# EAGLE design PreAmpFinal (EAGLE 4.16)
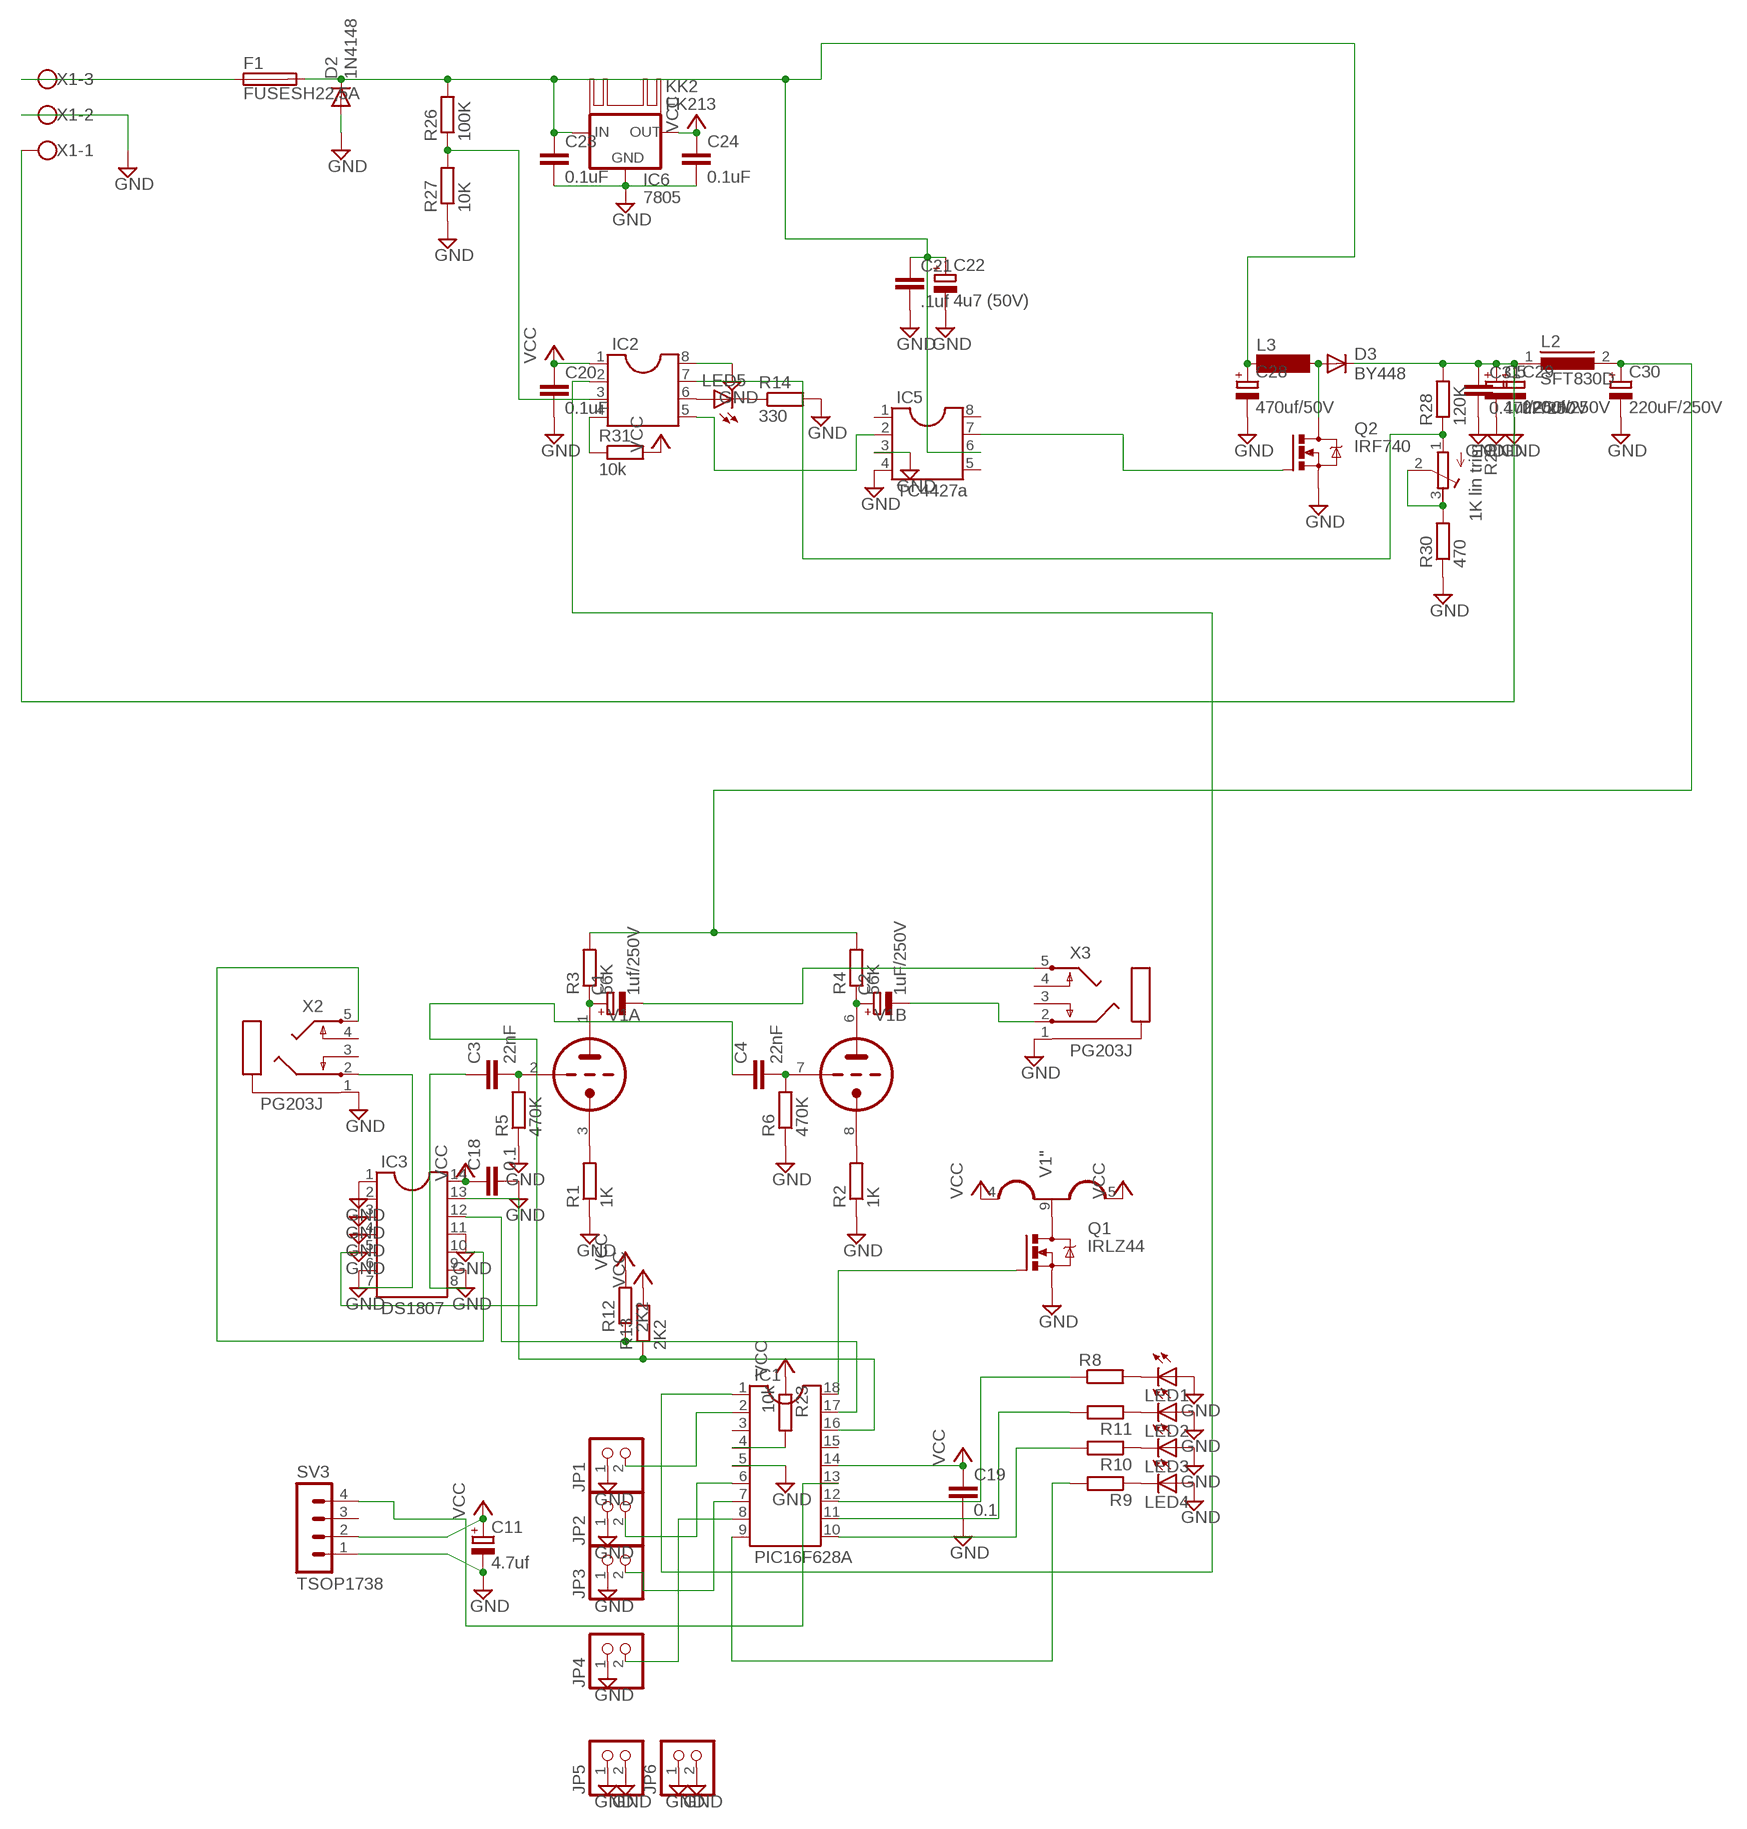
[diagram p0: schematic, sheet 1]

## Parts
C1  1uf/250V  CPOL-EUE2.5-7  [E2,5-7]
C2  1uF/250V  CPOL-EUE2.5-7  [E2,5-7]
C3  22nF  C7.5/4  [C7.5B4]
C4  22nF  C7.5/4  [C7.5B4]
C5  1uf/250V  CPOL-EUE2.5-7  [E2,5-7]
C11  4.7uf  CPOL-EUE2-5  [E2-5]
C18  0.1  C2.5/2  [C2.5-2]
C19  0.1  C2.5/2  [C2.5-2]
C20  0.1uF  C2.5/2  [C2.5-2]
C21  .1uf  C2.5/2  [C2.5-2]
C22  4u7 (50V)  CPOL-EUE2.5-5  [E2,5-5]
C23  0.1uF  C2.5/2  [C2.5-2]
C24  0.1uF  C2.5/2  [C2.5-2]
C28  470uf/50V  CPOL-EUE5-13  [E5-13]
C29  220uf/250V  CPOL-EUE10-22.5  [EB22,5D]
C30  220uF/250V  CPOL-EUE10-22.5  [EB22,5D]
C31  0.47uF/250V  C22/6  [C20.5B4]
D2  1N4148  [DO35-10]
D3  BY448  [SOD57-10]
F1  FUSESH22,5A  [SH22,5A]
IC1  PIC16F628A  DIL18S  [SOCKED-18]
IC2  DIL8S  [SOCKED-08]
IC3  DS1807  DIL14S  [SOCKED-14]
IC5  TC4427a  DIL8S  [SOCKED-08]
IC6  7805  78XXS  [78XXS]
JP1  PINHD-1X2  [1X02]
JP2  PINHD-1X2  [1X02]
JP3  PINHD-1X2  [1X02]
JP4  PINHD-1X2  [1X02]
JP5  PINHD-1X2  [1X02]
JP6  PINHD-1X2  [1X02]
KK2  FK213  [FK213]
L2  SFT830D  [SFT830D]
L3  18RXXX  [18R]
LED1  LED5MM  [LED5MM]
LED2  LED5MM  [LED5MM]
LED3  LED5MM  [LED5MM]
LED4  LED5MM  [LED5MM]
LED5  LED5MM  [LED5MM]
Q1  IRLZ44  IRF740  [TO220BV]
Q2  IRF740  [TO220BV]
R1  1K  R-EU_0204/7  [0204/7]
R2  1K  R-EU_0204/7  [0204/7]
R3  56K  R-EU_0204/7  [0204/7]
R4  56K  R-EU_0204/7  [0204/7]
R5  470K  R-EU_0204/7  [0204/7]
R6  470K  R-EU_0204/7  [0204/7]
R8  R-EU_0204/7  [0204/7]
R9  R-EU_0204/7  [0204/7]
R10  R-EU_0204/2V  [0204V]
R11  R-EU_0204/2V  [0204V]
R12  2K2  R-EU_0204/7  [0204/7]
R13  2K2  R-EU_0204/7  [0204/7]
R14  330  R-EU_0204/7  [0204/7]
R23  10k  R-EU_0204/7  [0204/7]
R26  100K  R-EU_0204/7  [0204/7]
R27  10K  R-EU_0204/7  [0204/7]
R28  120K  R-EU_0207/12  [0207/12]
R29  1K lin trim  R-TRIMM3339P  [RTRIM3339P]
R30  470  R-EU_0204/7  [0204/7]
R31  10k  R-EU_0204/7  [0204/7]
SV3  TSOP1738  MA04-1  [MA04-1]
V1  12AU7-P  [NOVAL]
X1  W237-3E  [W237-3E]
X2  PG203J  [PG203J]
X3  PG203J  [PG203J]

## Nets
GND: C5.- C11.- C18.2 C19.2 C20.2 C21.2 C22.- C23.2 C24.2 C28.- C29.- C30.- C31.2 D2.A IC1.5 IC2.8 IC3.1 IC3.2 IC3.3 IC3.4 IC3.6 IC3.9 IC3.11 IC5.3 IC5.4 IC6.GND JP1.1 JP2.1 JP3.1 JP4.1 JP5.1 JP5.2 JP6.1 JP6.2 LED1.A LED2.A LED3.A LED4.A Q1.S Q2.S R1.1 R2.1 R5.1 R6.1 R14.2 R27.1 R30.1 SV3.1 X1.2 X2.1 X3.1
N$1: C1.+ R3.1 V1.1(A:TA)
N$2: C2.+ R4.1 V1.6(B:TA)
N$3: R1.2 V1.3(A:TK)
N$4: R2.2 V1.8(B:TK)
N$5: Q1.D V1.9(":H2)
N$6: C3.2 R5.2 V1.2(A:TG)
N$7: C4.2 R6.2 V1.7(B:TG)
N$8: C30.+ L2.2 R3.2 R4.2
N$9: C3.1 IC3.8
N$10: IC2.4 R31.1
N$11: IC1.18 Q1.G
N$12: IC1.13 SV3.4
N$13: C2.- X3.2
N$14: LED1.K(C) R8.2
N$15: IC5.7 Q2.G
N$16: LED2.K(C) R11.1
N$17: LED3.K(C) R10.1
N$18: LED4.K(C) R9.1
N$19: IC1.2 JP1.2
N$22: F1.1 X1.3
N$23: IC1.12 R8.1
N$24: IC1.1 IC2.2
N$25: C4.1 IC3.5
N$26: IC1.17 IC3.12 R12.1
N$27: IC1.16 IC3.13 R13.1
N$28: IC3.7 X2.2
N$29: IC3.10 X2.5
N$30: IC1.11 R11.2
N$31: IC1.10 R10.2
N$32: IC2.6 LED5.A
N$33: IC1.9 R9.2
N$34: LED5.K(C) R14.1
N$35: C5.+ C29.+ C31.1 D3.C L2.1 R28.2 X1.1
N$36: C1.- X3.5
N$37: IC1.6 JP2.2
N$38: IC1.7 JP3.2
N$39: IC1.8 JP4.2
N$44: IC1.4 R23.2
N$48: IC2.5 IC5.2
N$49: IC2.3 R26.1 R27.2
N$53: IC2.7 R28.1 R29.1(E)
N$54: R29.2(S) R29.3(A) R30.2
N$56: D3.A L3.2 Q2.D
N$57: C21.1 C22.+ C23.1 C28.+ D2.C F1.2 IC5.6 IC6.IN L3.1 R26.2
VCC: C11.+ C18.1 C19.1 C20.1 C24.1 IC1.14 IC2.1 IC3.14 IC6.OUT R12.2 R13.2 R23.1 R31.2 SV3.2 V1.4(":H1) V1.5(":H3)
Unconnected: IC1.3 IC1.15 IC5.1 IC5.5 IC5.8 SV3.3 X2.3 X2.4 X3.3 X3.4

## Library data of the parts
C1 C2 C5 C11 C22 C28-C30 = rcl:CPOL-EU: POLARIZED CAPACITOR, European symbol
C3 C4 C18 C19 C31 = capacitor-HV:C: CAPACITOR
C20 C21 C23 C24 = capacitor-wima:C: CAPACITOR
D2 = diode:1N4148: DIODE
D3 = diode:BY448: DIODE
F1 = fuse:FUSE: Fuse
IC1 = ic-package:DIL18: Dual In Line
IC2 IC5 = ic-package:DIL8: Dual In Line
IC3 = ic-package:DIL14: Dual In Line
IC6 = v-reg:78XXS: VOLTAGE REGULATOR
JP1-JP6 = pinhead:PINHD-1X2: PIN HEADER
KK2 = heatsink:FK213: HEATSINK
L2 = inductors:SFT830D: INDUCTOR
L3 = inductor-neosid:18RXXX
LED1-LED5 = led:LED: LED
Q1 Q2 = transistor-power:IRF740: N-CHANNEL MOS FET
R1-R6 R8-R14 R23 R26-R28 R30 R31 = rcl:R-EU_: RESISTOR, European symbol
R29 = rcl:R-TRIMM: Trimm resistor
SV3 = con-lstb:MA04-1: PIN HEADER
V1 = tubes:12AU7-P
X1 = con-wago-508:W237-3E: WAGO SREW CLAMP
X2 X3 = con-hirschmann:PG203J: MIC/HEADPHONE JACK KS-S stereo microphone/headphone jack PG203JN (Schukat)

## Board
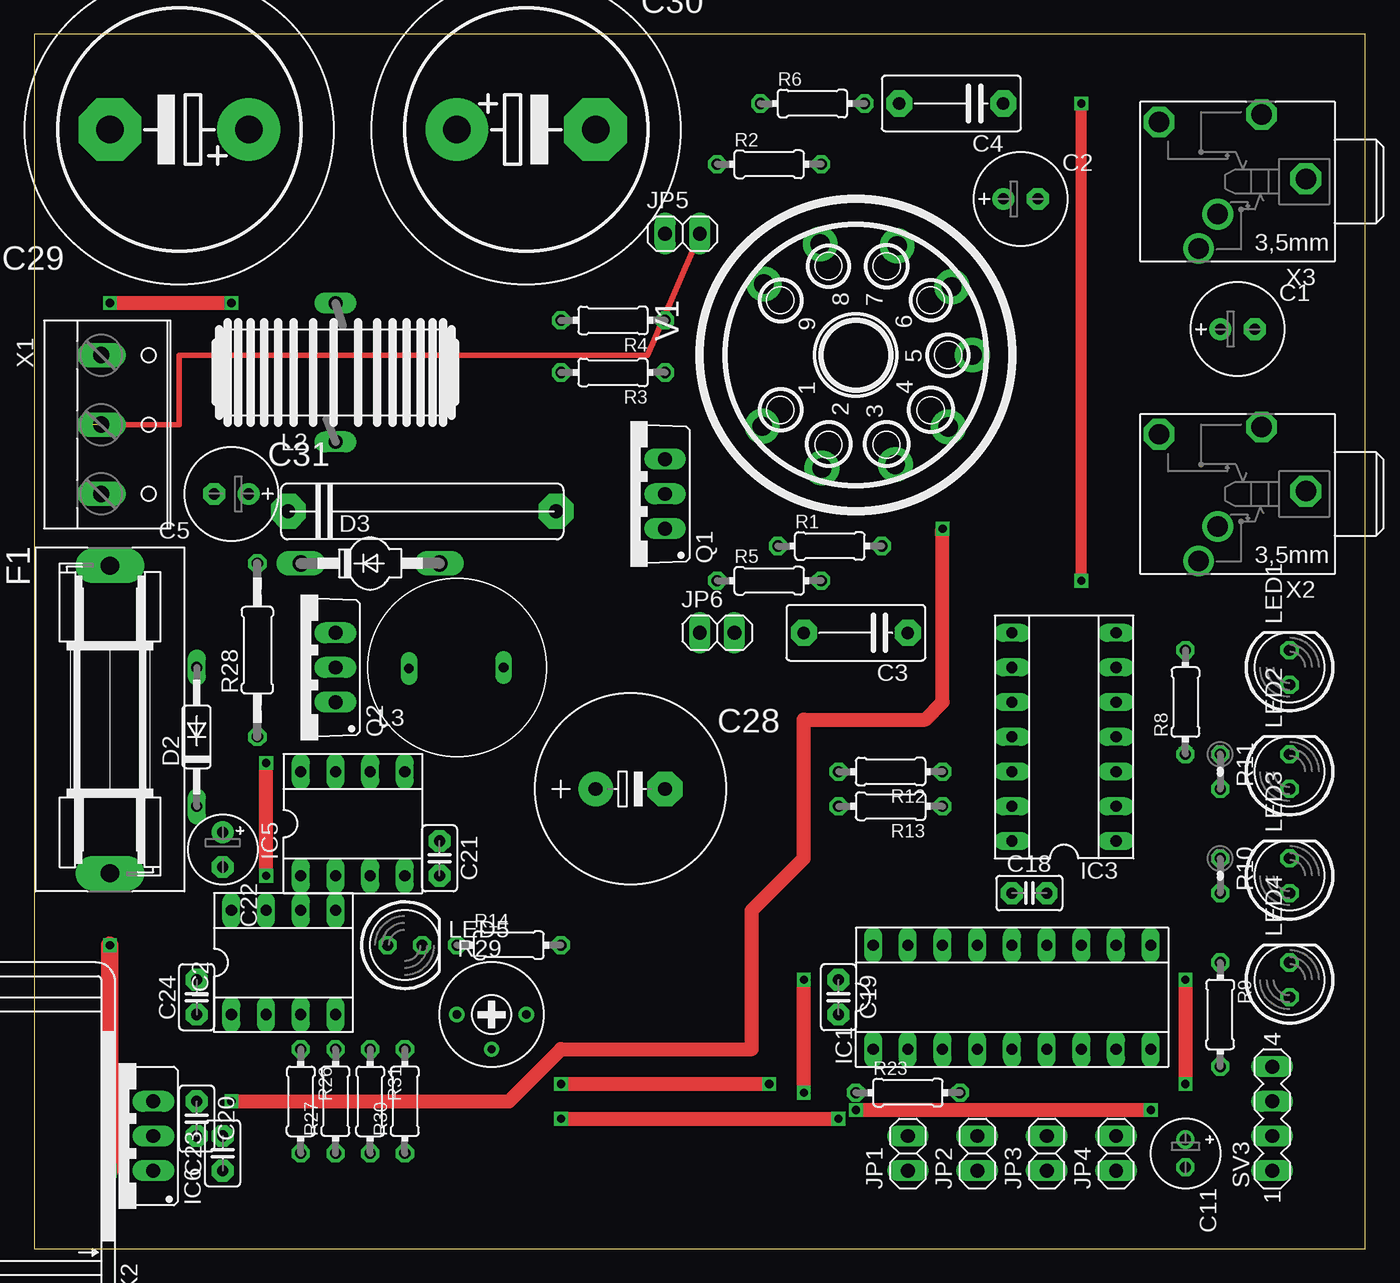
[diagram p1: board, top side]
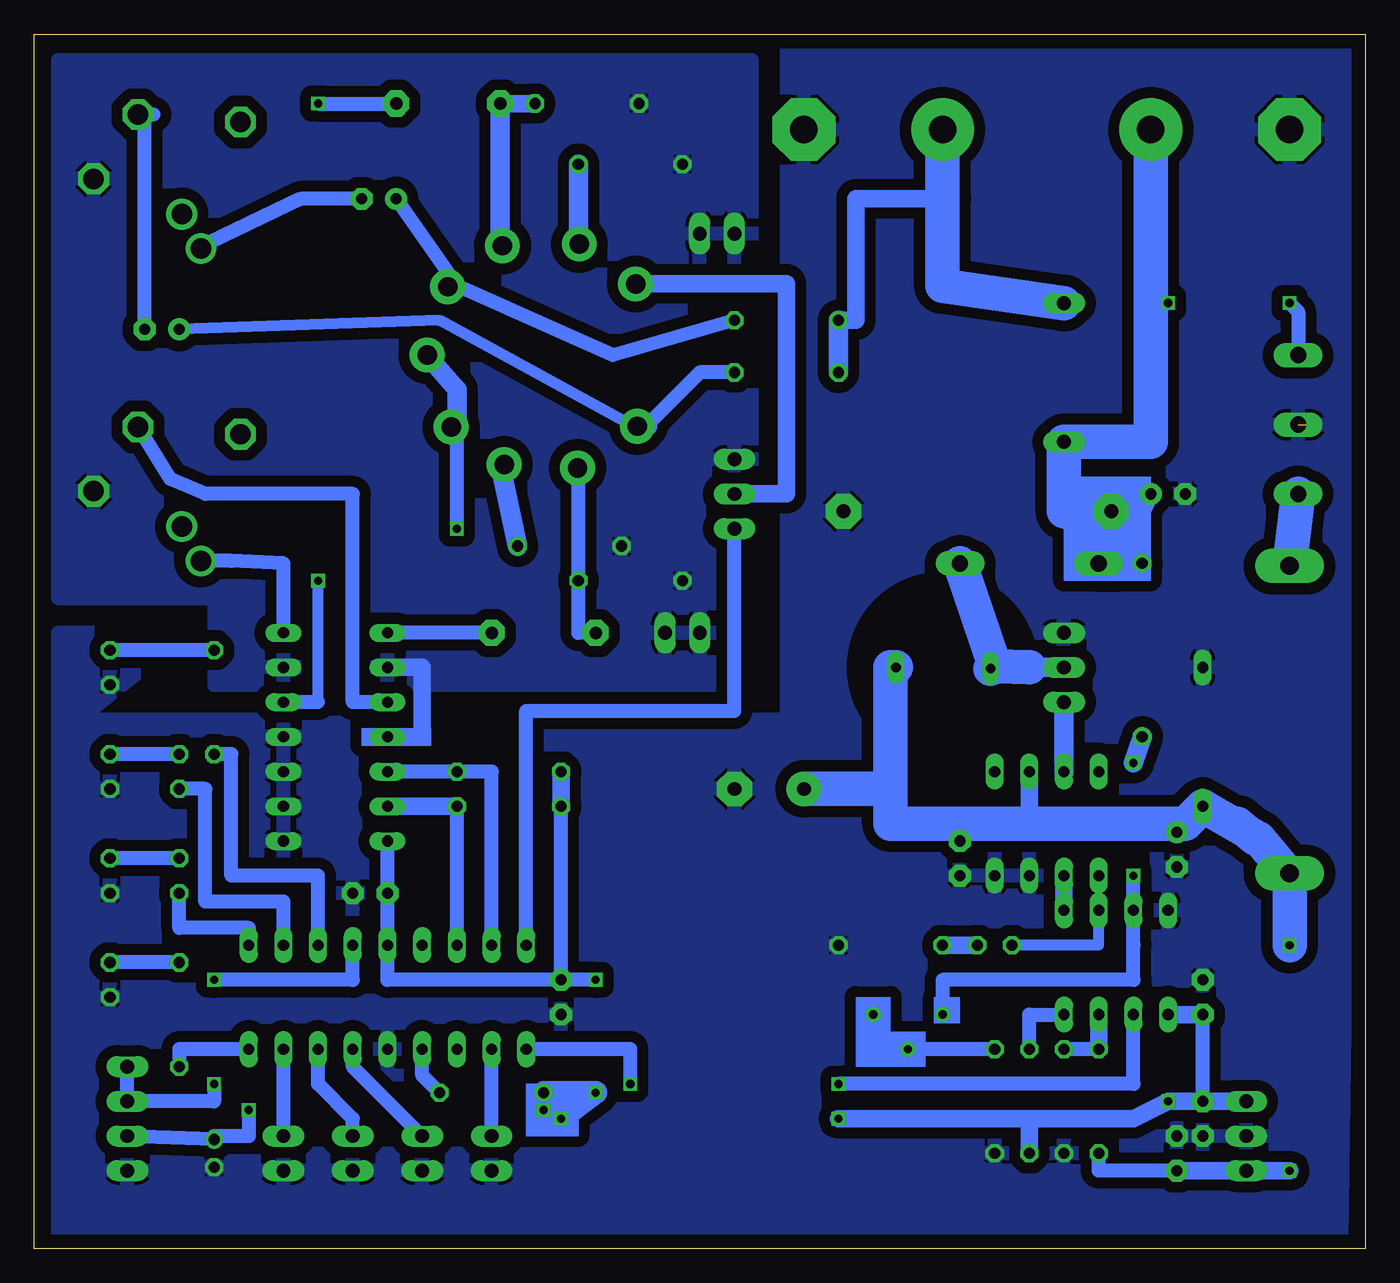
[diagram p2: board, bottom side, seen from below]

Size 97.46 x 88.89 mm. Coordinates in mm from the lower left corner, seen from the top.
Outline: 0,0 97.46,0 97.46,88.89 0,88.89 0,0
Copper layers (1*16): Top 0.035mm / dielectric 1.5mm / Bottom 0.035mm
Design rules "default": minimum track width 10mil, minimum drill 24mil, track to track 8mil, track to pad 8mil, pad to pad 8mil, via to via 8mil, smd to smd 8mil, copper to edge 40mil, drill to drill 8mil, minimum pad ring 10mil, minimum via ring 8mil, stop-mask expansion 4mil, vias tented up to drill 0mil, thermal gap 10mil
bRestrict: area 25.3,36.9 to 36.6,48.2

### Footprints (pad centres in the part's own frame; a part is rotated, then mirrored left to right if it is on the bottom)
E2,5-7 = drill 0.813 pad 1.6 round: + -1.27,0 | drill 0.813 pad 1.6 octagon: - 1.27,0
C7.5B4 = drill 0.914 pad 1.905 octagon: 1 -3.81,0; 2 3.81,0
E2-5 = drill 0.813 pad 1.27 round: + -1.016,0 | drill 0.813 pad 1.27 octagon: - 1.016,0
C2.5-2 = drill 0.813 pad 1.6 octagon: 1 -1.27,0; 2 1.27,0
E2,5-5 = drill 0.813 pad 1.6 round: + -1.27,0 | drill 0.813 pad 1.6 octagon: - 1.27,0
E5-13 = drill 1.016 pad 2.54 round: + -2.54,0 | drill 1.016 pad 2.54 octagon: - 2.54,0
EB22,5D = drill 2.007 pad 4.597 round: + -5.08,0 | drill 2.007 pad 4.597 octagon: - 5.08,0
C20.5B4 = drill 1.016 pad 2.54 octagon: 1 -9.803,0; 2 9.803,0
DO35-10 = drill 0.813 long: A 5.08,0; C -5.08,0
SOD57-10 = drill 1.194 long: A 5.08,0; C -5.08,0
SH22,5A = drill 1.321 pad 2.54 long: 1 -11.252,0; 2 11.252,0
SOCKED-18 = drill 0.813 long: 1 -10.16,-3.81; 2 -7.62,-3.81; 3 -5.08,-3.81; 4 -2.54,-3.81; 5 0,-3.81; 6 2.54,-3.81; 7 5.08,-3.81; 8 7.62,-3.81; 9 10.16,-3.81; 10 10.16,3.81; 11 7.62,3.81; 12 5.08,3.81; 13 2.54,3.81; 14 0,3.81; 15 -2.54,3.81; 16 -5.08,3.81; 17 -7.62,3.81; 18 -10.16,3.81
SOCKED-08 = drill 0.813 long: 1 -3.81,-3.81; 2 -1.27,-3.81; 3 1.27,-3.81; 4 3.81,-3.81; 5 3.81,3.81; 6 1.27,3.81; 7 -1.27,3.81; 8 -3.81,3.81
SOCKED-14 = drill 0.813 long: 1 -7.62,-3.81; 2 -5.08,-3.81; 3 -2.54,-3.81; 4 0,-3.81; 5 2.54,-3.81; 6 5.08,-3.81; 7 7.62,-3.81; 8 7.62,3.81; 9 5.08,3.81; 10 2.54,3.81; 11 0,3.81; 12 -2.54,3.81; 13 -5.08,3.81; 14 -7.62,3.81
78XXS = drill 1.016 long: GND 0,-2.54; IN -2.54,-2.54; OUT 2.54,-2.54
1X02 = drill 1.016 long: 1 -1.27,0; 2 1.27,0
SFT830D = drill 1.016 long: 1 -5.08,0; 2 5.08,0
18R = drill 0.7 long: 1 -3.415,0; 2 3.502,0.087
LED5MM = drill 0.813 octagon: A -1.27,0; K 1.27,0
TO220BV = drill 1.016 long: D 0,-2.54; G -2.54,-2.54; S 2.54,-2.54
0204/7 = drill 0.813 octagon: 1 -3.81,0; 2 3.81,0
0204V = drill 0.813 octagon: 1 -1.27,0; 2 1.27,0
0207/12 = drill 0.813 octagon: 1 -6.35,0; 2 6.35,0
RTRIM3339P = drill 0.61 round: 1 -2.54,0; 2 0,-2.54; 3 2.54,0
MA04-1 = drill 1.016 long: 1 -3.81,0; 2 -1.27,0; 3 1.27,0; 4 3.81,0
NOVAL = drill 1.422 pad 2.54 round: 1 5.207,-6.858; 2 8.254,-2.484; 3 8.004,2.893; 4 5.258,6.77; 5 0,8.524; 6 -5.004,7.024; 7 -8.004,3.02; 8 -8.127,-2.611; 9 -5.207,-6.731
W237-3E = drill 1.194 long: 1 -5.08,-0.635; 2 0,-0.635; 3 5.08,-0.635
PG203J = drill 1.499 octagon: 1 -5.004,-0.203; 4 5.74,-4.369; 5 -1.753,-4.902 | drill 1.499 round: 2 2.845,4.902; 3 1.448,2.388

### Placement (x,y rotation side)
C1  88.1,67.31 0 top
C2  72.22,76.83 0 top
C3  60.16,45.08 180 top
C4  67.14,83.81 180 top
C5  14.44,55.24 180 top
C11  84.29,6.98 270 top
C18  72.86,26.03 0 top
C19  58.89,18.41 270 top
C20  11.9,9.52 270 top
C21  29.68,28.57 270 top
C22  13.81,29.21 270 top
C23  13.81,6.98 90 top
C24  11.9,18.41 90 top
C28  43.65,33.65 0 top
C29  10.63,81.91 180 top
C30  36.03,81.91 0 top
C31  28.41,53.97 0 top
D2  11.9,37.46 90 top
D3  24.6,50.16 0 top
F1  5.55,38.73 270 top
IC1  71.59,18.41 0 top
IC2  18.25,20.95 0 top
IC3  75.4,37.46 90 top
IC5  23.33,31.11 0 top
IC6  6.18,8.25 90 top
JP1  63.97,6.98 90 top
JP2  69.05,6.98 90 top
JP3  74.13,6.98 90 top
JP4  79.21,6.98 90 top
JP5  47.46,74.29 0 top
JP6  50,45.08 0 top
KK2  4.92,8.25 90 top
L2  22.06,64.13 90 top
L3  30.95,42.54 180 top
LED1  91.91,42.54 90 top
LED2  91.91,34.92 90 top
LED3  91.91,27.3 90 top
LED4  91.91,19.68 90 top
LED5  27.14,22.22 0 top
Q1  43.65,55.24 90 top
Q2  19.52,42.54 90 top
R1  58.25,51.43 0 top
R2  53.81,79.37 0 top
R3  42.38,64.13 180 top
R4  42.38,67.94 180 top
R5  53.81,48.89 0 top
R6  56.98,83.81 0 top
R8  84.29,40 90 top
R9  86.83,17.14 270 top
R10  86.83,27.3 270 top
R11  86.83,34.92 270 top
R12  62.7,34.92 180 top
R13  62.7,32.38 180 top
R14  34.76,22.22 0 top
R23  63.97,11.43 0 top
R26  19.52,10.79 270 top
R27  22.06,10.79 90 top
R28  16.34,43.81 90 top
R29  33.49,17.14 0 top
R30  27.14,10.79 90 top
R31  24.6,10.79 270 top
SV3  90.64,9.52 90 top
V1  60.16,65.4 270 top
X1  5.55,60.32 270 top
X2  88.1,55.24 180 top
X3  88.1,78.1 180 top

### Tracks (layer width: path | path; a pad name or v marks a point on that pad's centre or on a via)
GND  (1 unrouted)
  Top 0.406: JP5.2 44.92,65.4 10.63,65.4 10.63,60.32 4.28,60.32
  Bottom 1.27: IC3.11 69.05,37.46 69.05,42.54 IC3.9
  pour Bottom (isolate 0.813): 42.38,88.26 42.38,38.73 95.72,38.73 95.72,0.63 1.74,0.63 0.47,88.26
  pour Bottom (isolate 0.813): 44.92,86.99 95.72,86.99 95.72,47.62 84.29,47.62 84.29,41.27 44.92,41.27
  pour Bottom (isolate 0.813): 86.19,45.08 95.72,45.08 95.72,37.46
N$1
  Bottom 0.813: V1.1 53.17,60.32 53.81,60.32 67.78,67.94 C1.+
  Bottom 1.016: 52.54,60.19 52.54,60.32 48.73,64.13 R3.1
  Bottom 1.422: 52.54,60.19 V1.1
N$2
  Bottom 1.016: 66.51,70.48 67.14,70.48 | 66.51,70.48 55.08,65.4 R4.1 | 66.51,70.48 C2.+
  Bottom 1.422: V1.6 67.14,70.4 67.14,70.48
N$3
  Bottom 1.422: V1.3 63.34,57.4 R1.2
N$4
  Bottom 1.016: 57.62,73.66 57.55,73.58 V1.8
  Bottom 1.422: R2.2 57.62,73.66 57.62,73.02
N$5
  Bottom 1.016: 53.81,70.48 53.81,70.61 V1.9
  Bottom 1.27: 53.81,70.61 42.38,70.61 42.38,55.24 Q1.D
N$6
  Bottom 1.016: C3.2 57.62,45.08 R5.2 57.62,57.14 | 57.62,57.14 57.62,57.78 | 57.62,57.14 57.62,57.15
  Bottom 1.422: 57.62,57.15 V1.2
N$7
  Bottom 1.27: C4.2 R6.2
  Bottom 1.422: 63.34,73.4 63.34,73.02 | V1.7 63.34,73.4 | 63.34,73.4 C4.2
N$8
  Bottom 1.27: R4.2 37.3,67.94 37.3,76.83 30.95,76.83
  Bottom 1.422: R4.2 R3.2
  Bottom 2.54: L2.2 30.95,70.48 30.95,76.83 C30.+
N$9
  Bottom 1.016: C3.1 IC3.8
N$10
  Bottom 1.016: R31.1 24.6,17.14 IC2.4
N$11
  Bottom 1.016: IC1.18 61.43,39.36 46.19,39.36 Q1.G
N$12  (via drill 0.6)
  Top 1.016: v84.29,19.68 v84.29,12.06
  Bottom 1.016: SV3.4 90.64,10.79 84.29,10.79 v84.29,12.06 | IC1.13 74.13,19.68 v84.29,19.68
N$13
  Bottom 1.016: X3.2 85.56,73.2 77.94,76.83 C2.-
N$14
  Bottom 1.016: R8.2 LED1.K
N$15
  Bottom 1.422: IC5.7 Q2.G
N$16
  Bottom 1.016: R11.1 LED2.K
N$17
  Bottom 1.016: R10.1 LED3.K
N$18
  Bottom 1.016: R9.1 LED4.K
N$19
  Bottom 1.016: JP1.2 IC1.2
N$22
  Bottom 2.54: X1.3 5.55,50.16 F1.1
N$23  (via drill 0.6)
  Bottom 1.016: IC1.12 76.67,27.3 83.02,27.3 83.02,36.19 R8.1
  other vias: 84.29,36.19 84.29,36.19
N$24  (via drill 0.6)
  Top 1.016: v38.57,12.06 v53.81,12.06
  Bottom 1.016: IC2.2 16.98,12.06 v38.57,12.06 | v53.81,12.06 53.81,14.6 IC1.1
N$25  (via drill 0.6)
  Top 0.813: v76.67,48.89 v76.67,83.81
  Bottom 0.813: 76.67,40 v76.67,48.89
  Bottom 1.016: 76.67,40 IC3.5 | v76.67,83.81 C4.1
N$26
  Bottom 1.016: IC3.12 R12.1 63.97,34.92 IC1.17
N$27
  Bottom 1.016: IC1.16 R13.1
  Bottom 1.27: R13.1 IC3.13
N$28
  Bottom 1.016: X2.2 83.02,50.34 79.21,50.16 IC3.7
N$29
  Bottom 1.016: X2.5 87.47,56.33 84.92,55.24 74.13,55.24 74.13,40 IC3.10
N$30
  Bottom 1.016: IC1.11 79.21,25.39 84.92,25.39 84.92,33.65 R11.2
N$31
  Bottom 1.016: R10.2 86.83,23.49 81.75,23.49 IC1.10
N$32
  Bottom 0.813: IC2.6 19.52,22.22 LED5.A
N$33
  Bottom 1.016: R9.2 86.83,14.6 IC1.9
N$34
  Bottom 1.27: LED5.K R14.1
N$35  (via drill 0.6)
  Top 1.016: v14.44,69.21 v5.55,69.21
  Bottom 1.016: X1.1 4.92,68.58 v5.55,69.21 | 15.71,69.21 v14.44,69.21
  Bottom 1.27: 18.25,50.16 C5.+ | R28.2 D3.C
  Bottom 2.54: 18.25,52.7 C31.1 22.06,53.97 | D3.C 18.25,50.16 18.25,52.7 | 18.25,52.7 22.06,53.97 | 22.06,53.97 L2.1 15.71,59.05 15.71,69.21 C29.+
N$36
  Bottom 1.016: C1.- 89.37,83.18 90,83.18 88.73,83 X3.5
N$37
  Bottom 1.016: IC1.6 74.13,13.33 JP2.2
N$38
  Bottom 1.016: JP3.2 74.13,9.52 76.67,12.06 IC1.7
N$39
  Bottom 1.016: JP4.2 IC1.8
N$44
  Bottom 1.016: IC1.4 69.05,12.7 R23.2
N$48
  Bottom 1.27: IC2.5 IC5.2
N$49
  Bottom 1.016: R26.1 R27.2
  Bottom 1.27: R26.1 IC2.3
N$53  (via drill 0.6)
  Top 1.016: v16.98,27.3 v16.98,35.55
  Bottom 1.016: R29.1 30.95,19.68 16.98,19.68 16.98,22.22 | 16.98,22.22 IC2.7 | 16.98,22.22 v16.98,27.3
  Bottom 1.422: v16.98,35.55 R28.1
N$54
  Bottom 1.016: R30.2 R29.2 36.03,14.6 R29.3
N$56
  Bottom 1.422: Q2.D 24.6,42.54
  Bottom 2.54: 27.14,42.63 L3.2 | 24.6,42.54 27.14,42.63 | 27.14,42.63 D3.A
N$57  (via drill 0.6)
  Top 1.27: v5.55,5.71 v5.55,22.22
  Bottom 1.016: C23.1 19.52,5.71 R26.2
  Bottom 1.27: v5.55,5.71 C23.1 IC6.IN | 24.6,31.11 IC5.6 | 29.68,31.11 C21.1 | 13.17,31.11 C22.+
  Bottom 2.54: 5.55,27.3 F1.2 | 5.55,27.3 7.84,30.05 | 7.84,30.05 D2.C 13.17,31.11 24.6,31.11 29.68,31.11 34.76,31.11 34.76,33.65 | v5.55,22.22 5.55,27.3 | 9.36,31.11 8.09,30.05 7.84,30.05 | L3.1 34.76,42.54 34.76,33.65 | 34.76,33.65 C28.+
VCC  (via drill 0.6)
  Top 1.016: v56.35,11.43 v56.35,19.68 | v38.57,9.52 v58.89,9.52 | v60.16,10.16 v81.75,10.16 | v66.51,52.7 66.51,40 65.24,38.73 56.35,38.73 56.35,28.57 52.54,24.76 52.54,14.6 38.57,14.6 34.76,10.79 v14.44,10.79
  Bottom 1.016: SV3.2 C11.+ 84.29,8.25 81.75,8.25 v81.75,10.16 | C24.1 C20.1 v14.44,10.79 | IC1.14 71.59,19.68 C19.1 | v66.51,52.7 66.51,60.32 | IC1.14 C18.1 IC3.14 IC1.14 | v58.89,9.52 v60.16,10.16 | v56.35,19.68 C19.1 | C19.1 R12.2
  Bottom 1.27: C20.1 IC6.OUT C20.1 | C24.1 IC2.1 | R12.2 R13.2 | 24.6,9.52 R31.2 | 24.6,9.52 v38.57,9.52 | C20.1 v14.44,10.79 16.98,9.52 24.6,9.52
  Bottom 1.422: V1.4 66.51,60.14 66.51,60.32 66.51,62.86 V1.5
  Bottom 1.676: v58.89,9.52 v56.35,11.43 R23.1
  other vias: 71.59,26.03
(copper drawn outside any net)
  shapes: Bottom area x7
